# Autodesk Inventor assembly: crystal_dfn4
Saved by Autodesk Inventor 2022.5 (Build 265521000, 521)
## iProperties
Created: 2024-12
Part Number: crystal_dfn4
Document SubType Name: Assembly
Designer: AdminForWorker
Title: crystal_dfn4 v1
Author: AdminForWorker
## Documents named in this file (5)
- c:\worker\convert-fusion-r05-cosv3\tmp\job-1\35\temp\files\545dca92-a972-481a-9197-dd1a1176500e\crystal_dfn4 v1.iam
- c:\worker\convert-fusion-r05-cosv3\tmp\job-1\35\temp\files\545dca92-a972-481a-9197-dd1a1176500e\Component2.ipt
- c:\worker\convert-fusion-r05-cosv3\tmp\job-1\35\temp\files\545dca92-a972-481a-9197-dd1a1176500e\Component3.ipt
- c:\worker\convert-fusion-r05-cosv3\tmp\job-1\35\temp\files\545dca92-a972-481a-9197-dd1a1176500e\Component4.ipt
- c:\worker\convert-fusion-r05-cosv3\tmp\job-1\35\temp\files\545dca92-a972-481a-9197-dd1a1176500e\Component5_2.ipt
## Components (4 placed, 4 different names)
1. Component2:1
2. Component3:1
3. Component4:1
4. Component5:1
